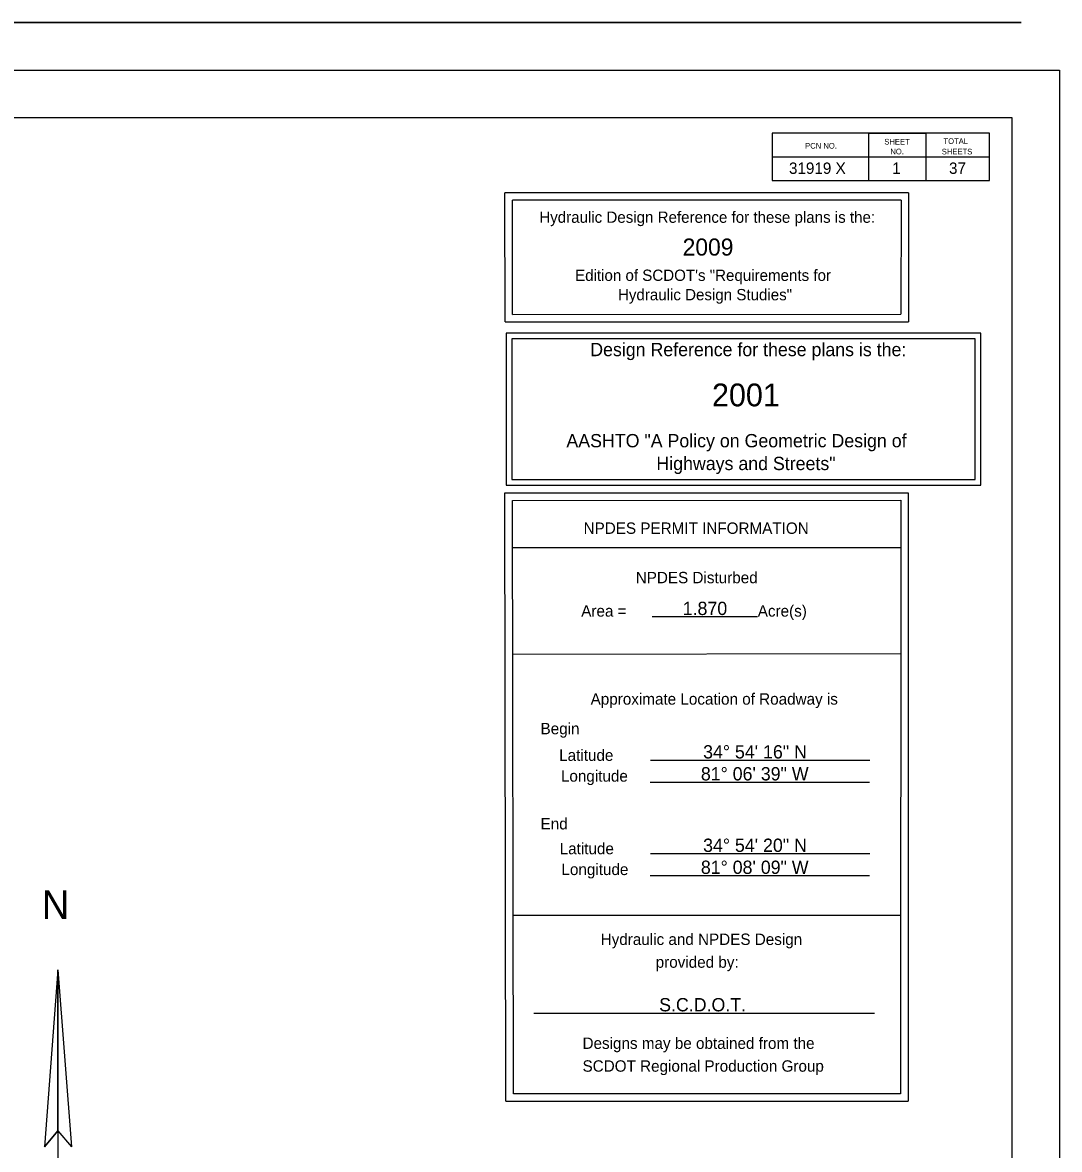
# Model space of a CAD drawing. Extents: x -796 to 2793, y -4650 to 4425.
# Drawn here: x 2234 to 2780, y 1532 to 2125 of the extents above; entities that cross this region are included whole.
import ezdxf

# ---------------------------------------------------------------- set-up
doc = ezdxf.new("R2010")
doc.units = 0
for name, color, linetype in [('RD_EX_Misc', 7, 'Continuous'), ('RD_HC_CL', 7, 'Continuous'), ('RD_HC_Data', 7, 'Continuous'), ('RD_HC_Data_Tic', 7, 'Continuous'), ('RD_SHT_Bndy', 7, 'Continuous')]:
    doc.layers.add(name, color=color, linetype=linetype)

msp = doc.modelspace()

# ---------------------------------------------------------------- linework, layer by layer
at = {"layer": 'RD_EX_Misc'}
for p, q in [((2252.53, 1626.13), (2245.58, 1532.83)), ((2252.53, 1626.13), (2259.78, 1532.83)), ((2252.53, 1626.13), (2252.53, 1415.43)), ((2252.53, 1541.38), (2245.58, 1532.83)), ((2252.53, 1541.38), (2259.78, 1532.83))]:
    msp.add_line(p, q, dxfattribs=at)
msp.add_lwpolyline([(2252.53, 1541.38), (2252.53, 1626.13), (2245.58, 1532.83), (2252.53, 1541.38)], dxfattribs=at)
at = {"layer": 'RD_HC_CL'}
msp.add_lwpolyline([(984.13, 2100), (2780.13, 2100), (2780.13, 1000), (984.13, 1000)], close=True, dxfattribs=at)
at = {"layer": 'RD_HC_Data'}
for p, q in [((1000, 2125), (2759.98, 2125)), ((2760, 2125), (1000, 2125)), ((1000, 2100), (2759.98, 2100)), ((2743.28, 2066.8), (2628.78, 2066.8)), ((2628.78, 2066.8), (2628.78, 2041.8)), ((2679.78, 2041.8), (2679.78, 2066.8)), ((2679.78, 2066.8), (2709.78, 2066.8)), ((2709.78, 2066.8), (2709.78, 2041.8)), ((2743.28, 2041.8), (2743.28, 2066.8)), ((2628.78, 2054.3), (2742.93, 2054.3)), ((2628.78, 2041.8), (2743.28, 2041.8)), ((2649.78, 2041.8), (2700.78, 2041.8)), ((2700.61, 2035.37), (2488.08, 2035.37)), ((2488.16, 1967.38), (2488.08, 2035.37)), ((2492.13, 1971.32), (2492.04, 2031.43)), ((2696.68, 2031.43), (2492.04, 2031.43)), ((2696.68, 2031.43), (2696.65, 1971.38)), ((2700.61, 2035.37), (2700.59, 1967.43)), ((2492.13, 1971.32), (2696.65, 1971.38)), ((2488.16, 1967.38), (2700.59, 1967.43)), ((2488.1, 1877.27), (2700.53, 1877.33)), ((2488.47, 1556.89), (2488.1, 1877.27)), ((2700.53, 1877.33), (2700.45, 1556.89)), ((2492.08, 1873.27), (2696.59, 1873.45)), ((2492.55, 1560.84), (2492.08, 1873.27)), ((2696.59, 1873.45), (2696.42, 1560.76)), ((2492.23, 1848.53), (2696.55, 1848.5)), ((2565.56, 1812.15), (2621.11, 1812.15)), ((2492.2, 1792.36), (2696.41, 1792.63)), ((2564.72, 1736.58), (2680.27, 1736.58)), ((2564.52, 1725), (2680.08, 1725)), ((2564.72, 1687.37), (2680.27, 1687.37)), ((2564.52, 1675.78), (2680.08, 1675.78)), ((2696.52, 1654.78), (2492.41, 1654.78)), ((2503.27, 1603.36), (2682.71, 1603.36)), ((2696.42, 1560.76), (2492.55, 1560.84))]:
    msp.add_line(p, q, dxfattribs=at)
msp.add_lwpolyline([(1079.63, 2075.05), (2755.13, 2075.05), (2755.13, 1025), (1079.63, 1025)], close=True, dxfattribs=at)
msp.add_lwpolyline([(2488.47, 1556.89), (2700.45, 1556.89)], dxfattribs=at)
at = {"layer": 'RD_SHT_Bndy'}
for points in [[(2488.74, 1881.42), (2738.74, 1881.42), (2738.74, 1961.42), (2488.74, 1961.42)], [(2491.74, 1884.42), (2735.74, 1884.42), (2735.74, 1958.42), (2491.74, 1958.42)]]:
    msp.add_lwpolyline(points, close=True, dxfattribs=at)

# ---------------------------------------------------------------- texts
at = {"layer": 'RD_EX_Misc'}
msp.add_text('N', height=15, dxfattribs=at).set_placement((2244.14, 1652.98))
at = {"layer": 'RD_HC_Data_Tic'}
for s, height, p in [('PCN NO.', 3, (2646.2, 2058.59)), ('SHEET', 3, (2687.87, 2060.73)), ('TOTAL', 3, (2719.05, 2061.05)), ('NO.', 3, (2691.05, 2055.57)), ('SHEETS', 3, (2718.16, 2055.53)), ('NPDES PERMIT INFORMATION', 6, (2529.51, 1855.72)), ('NPDES Disturbed', 6, (2556.97, 1829.71)), ('Area =                               Acre(s)', 6, (2528.27, 1812.14)), ('Approximate Location of Roadway is', 6, (2533.21, 1765.77)), ('Begin', 6, (2506.84, 1750.18)), ('Latitude', 6, (2516.64, 1736.18)), ('Longitude', 6, (2517.57, 1725.22)), ('End', 6, (2506.84, 1700.07)), ('Latitude', 6, (2516.92, 1687)), ('Longitude', 6, (2517.85, 1676.04)), ('Hydraulic and NPDES Design', 6, (2538.5, 1639.22)), ('             provided by:', 6, (2538.5, 1627.21)), ('Designs may be obtained from the ', 6, (2528.95, 1584.49)), ('SCDOT Regional Production Group', 6, (2528.95, 1572.48))]:
    msp.add_text(s, height=height, dxfattribs=at).set_placement(p)
at = {"layer": 'RD_SHT_Bndy'}
for s, height, p in [('31919 X', 6, (2637.67, 2045.3)), ('1', 6, (2692.03, 2045.3)), ('37', 6, (2721.96, 2045.3)), ('Hydraulic Design Reference for these plans is the:', 5.9493, (2506.16, 2019.53)), ('2009', 9, (2581.66, 2002.26)), ('Edition of SCDOT\'s "Requirements for ', 5.9493, (2525.02, 1988.93)), ('Hydraulic Design Studies"', 5.9493, (2547.6, 1978.73)), ('Design Reference for these plans is the:', 7, (2533, 1949.3)), ('2001', 12, (2597.14, 1922.88)), ('AASHTO "A Policy on Geometric Design of ', 7, (2520.45, 1901.3)), ('Highways and Streets"', 7, (2567.84, 1889.3)), ('1.870', 7, (2581.71, 1812.98)), ('34%%d 54\' 16" N', 7, (2592.46, 1737.44)), ('81%%d 06\' 39" W', 7, (2591.28, 1725.88)), ('34%%d 54\' 20" N', 7, (2592.46, 1688.23)), ('81%%d 08\' 09" W', 7, (2591.28, 1676.64)), ('S.C.D.O.T.', 7, (2569.3, 1604.26))]:
    msp.add_text(s, height=height, dxfattribs=at).set_placement(p)

doc.saveas('drawing.dxf')
